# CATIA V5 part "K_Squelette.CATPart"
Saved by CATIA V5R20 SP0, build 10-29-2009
Part number: Squelette
Publications: "plan_sym", "Plan_bielle2", "Plan_godet", "Centre_bras/godet", "Centre_bras/bielle2", "Centre_verin/bielle2", "Centre_bielle2/bielette", "Centre_bielette/godet", "Plan.4"
Bounding box of the stored display mesh (mm): x 0 to 21, y 21.719 to 246.47, z 77.441 to 171.511
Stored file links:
  G:\Khaled_CFAO_2011\ST2M\ST2M_GR1\hgrenier\Khaled\CAD_ThinkMOTION\K_Squelette.CATPart
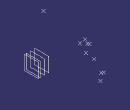
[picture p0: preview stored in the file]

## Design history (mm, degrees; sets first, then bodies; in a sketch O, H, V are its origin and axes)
Set1 "set_geo1"
  Plane1 "plan_sym": type Offset, RefPlane yz-plane, Offset 0
  Plane2 "Plan_bielle2": type Offset, RefPlane Plane1, Offset 15
  Plane3 "Plan_godet": type Offset, RefPlane Plane1, Offset 21
  Point1 "Centre_bras/godet": type OnPlane, Support Plane1, H 184.534, V 150.027, Direction (0, 1, 0)
  Point2 "Centre_bras/bielle2": type OnPlane, Support Plane2, H 165.417, V 150.684, Direction (0, 1, 0)
  Point3 "Centre_verin/bielle2": type OnPlane, Support Plane2, H 184.816, V 171.511, Direction (0, 1, 0)
  Point4 "Centre_bielle2/bielette": type OnPlane, Support Plane2, H 192.173, V 162.375, Direction (0, 1, 0)
  Point5 "Centre_bielette/godet": type OnPlane, Support Plane3, H 193.142, V 137.987, Direction (0, 1, 0)
  Point6 "Centre_bras_verin1": type OnPlane, Support Plane1, H 21.719, V 169.887, Direction (0, 1, 0)
  Plane4: type Offset, RefPlane Plane1, Offset 15, reversed
  Point7 "Centre_godet/verin2": type OnPlane, Support Plane3, H 223.049, V 133.683, Direction (0, 1, 0)
  Point8 "Centre_godet/bielette2": type OnPlane, Support Plane3, H 246.47, V 103.773, Direction (0, 1, 0)
  Point9 "Centre_bielette2/tête": type OnPlane, Support Plane3, H 244.422, V 77.441, Direction (0, 1, 0)
  Point10 "Centre_verin2/tête": type OnPlane, Support Plane1, H 235.708, V 89.158, Direction (0, 1, 0)
Body1 (main body)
